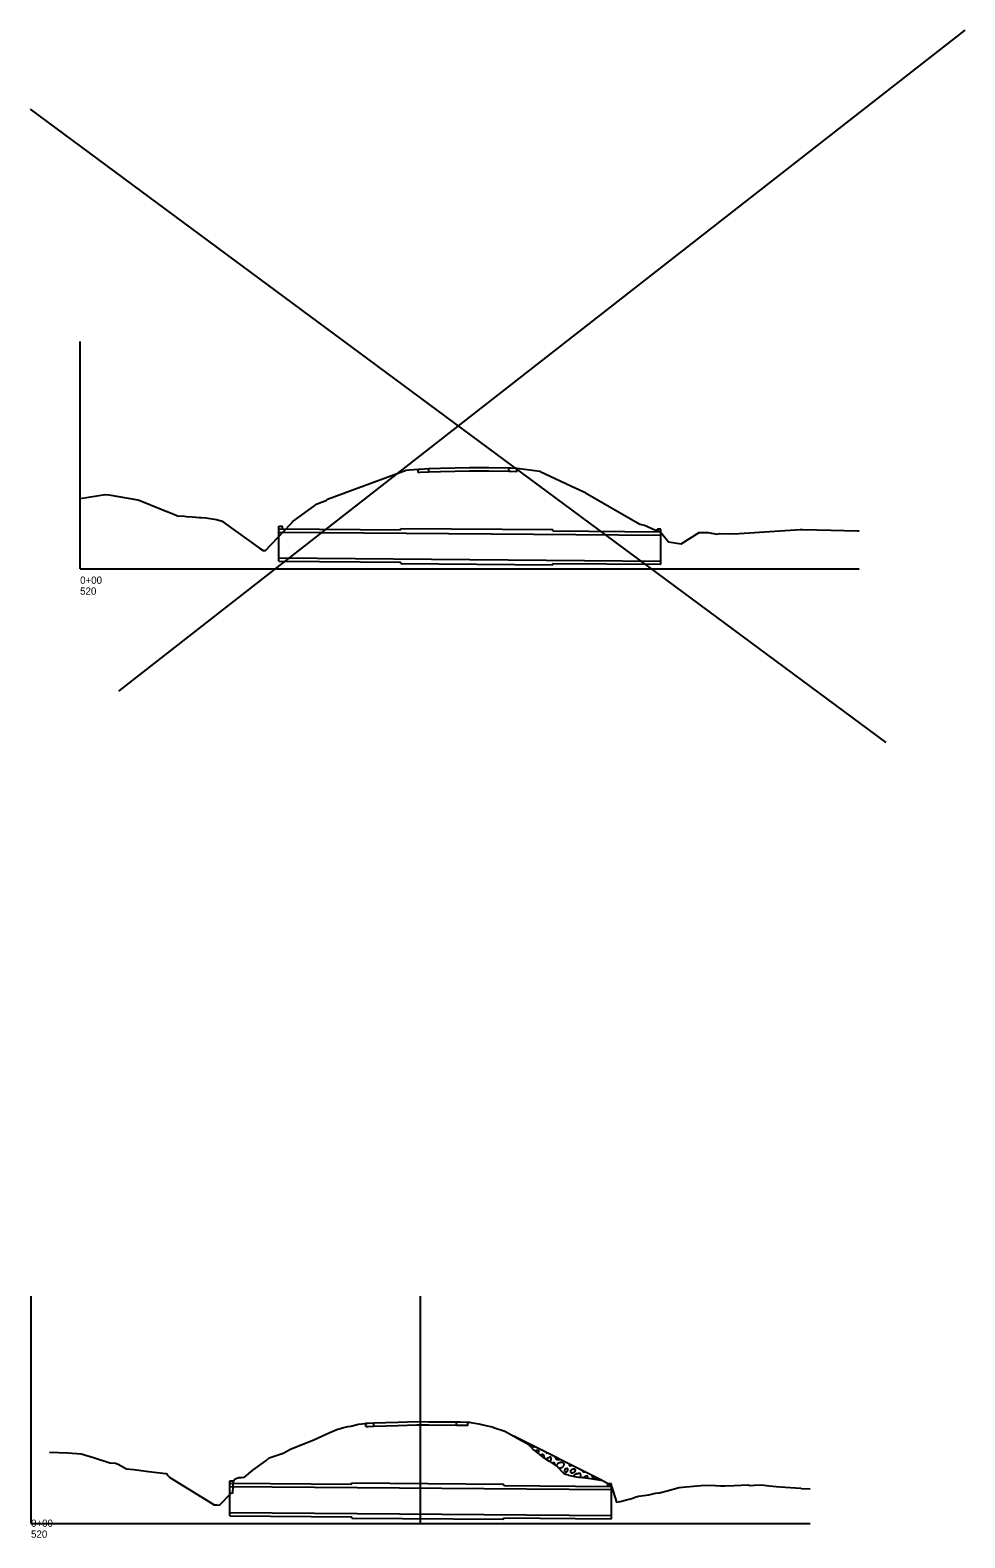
# Model space of a CAD drawing. Extents: x 2047712 to 2051245, y 280285 to 283042.
# Drawn here: x 2048516 to 2048876, y 282462 to 283042 of the extents above; entities that cross this region are included whole.
import ezdxf

# ---------------------------------------------------------------- set-up
doc = ezdxf.new("R2010")
doc.units = 0
for name, color, linetype in [('PM_X_Stop_Line', 7, 'Continuous'), ('PV_X_EOP', 7, 'Continuous'), ('SV_X_Mon_Cells_Found', 7, 'Continuous'), ('SV_X_Text', 7, 'Continuous'), ('UT_X_Water_Cells', 7, 'Continuous')]:
    doc.layers.add(name, color=color, linetype=linetype)

msp = doc.modelspace()

# ---------------------------------------------------------------- linework, layer by layer
at = {"layer": 'PM_X_Stop_Line'}
for p, q in [((2048875.63, 283042.02), (2048549.75, 282787.57)), ((2048515.73, 283011.56), (2048845.19, 282767.86)), ((2048534.97, 282834.64), (2048534.97, 282922.17)), ((2048534.97, 282834.64), (2048834.97, 282834.64)), ((2048516.07, 282467.2), (2048516.07, 282554.73)), ((2048666.07, 282467.2), (2048666.07, 282554.73)), ((2048516.07, 282467.2), (2048816.07, 282467.2))]:
    msp.add_line(p, q, dxfattribs=at)
at = {"layer": 'PV_X_EOP'}
for p, q in [((2048665.18, 282871.78), (2048665.18, 282873.03)), ((2048669.25, 282872.06), (2048669.25, 282873.31)), ((2048700.04, 282872.31), (2048700.04, 282873.56)), ((2048703.13, 282872.15), (2048703.13, 282873.4)), ((2048644.95, 282504.49), (2048644.95, 282505.74)), ((2048648.11, 282504.61), (2048648.11, 282505.86)), ((2048679.84, 282505.04), (2048679.84, 282506.29)), ((2048684.23, 282504.97), (2048684.23, 282506.22))]:
    msp.add_line(p, q, dxfattribs=at)
for points in [[(2048665.18, 282871.78), (2048665.89, 282871.84), (2048669.25, 282872.06), (2048673.74, 282872.15), (2048684.87, 282872.4), (2048692.39, 282872.41), (2048700.04, 282872.31), (2048700.87, 282872.3), (2048703.13, 282872.15), (2048703.13, 282872.15)], [(2048644.95, 282504.49), (2048645.82, 282504.52), (2048648.11, 282504.61), (2048657.25, 282504.88), (2048664.56, 282505.12), (2048669.3, 282505.09), (2048679.84, 282505.04), (2048681.33, 282505.02), (2048684.23, 282504.97), (2048684.23, 282504.97)]]:
    msp.add_lwpolyline(points, dxfattribs=at)
at = {"layer": 'SV_X_Mon_Cells_Found'}
for p, q in [((2048611.5, 282837.59), (2048611.5, 282851.09)), ((2048611.5, 282851.09), (2048612.94, 282851.09)), ((2048611.5, 282850.09), (2048658.5, 282849.71)), ((2048612.94, 282850.08), (2048612.94, 282851.09)), ((2048658.5, 282850.21), (2048717.03, 282849.74)), ((2048658.5, 282849.71), (2048658.5, 282850.21)), ((2048717.03, 282849.24), (2048717.03, 282849.74)), ((2048717.03, 282849.24), (2048758.53, 282848.91)), ((2048757.1, 282848.92), (2048757.1, 282849.91)), ((2048758.53, 282849.91), (2048757.1, 282849.91)), ((2048758.53, 282836.41), (2048758.53, 282849.91)), ((2048611.5, 282848.84), (2048758.53, 282847.66)), ((2048611.5, 282838.84), (2048758.53, 282837.66)), ((2048611.5, 282837.59), (2048658.5, 282837.21)), ((2048658.5, 282836.71), (2048658.5, 282837.21)), ((2048658.5, 282836.71), (2048717.03, 282836.24)), ((2048717.03, 282836.24), (2048717.03, 282836.74)), ((2048717.03, 282836.74), (2048758.53, 282836.41)), ((2048592.6, 282470.15), (2048592.6, 282483.65)), ((2048592.6, 282483.65), (2048594.03, 282483.65)), ((2048594.03, 282482.64), (2048594.03, 282483.65)), ((2048592.6, 282482.65), (2048639.6, 282482.27)), ((2048592.6, 282481.4), (2048739.62, 282480.22)), ((2048639.6, 282482.77), (2048698.12, 282482.3)), ((2048639.6, 282482.27), (2048639.6, 282482.77)), ((2048698.12, 282481.8), (2048698.12, 282482.3)), ((2048698.12, 282481.8), (2048739.62, 282481.47)), ((2048738.19, 282481.48), (2048738.19, 282482.47)), ((2048739.62, 282482.47), (2048738.19, 282482.47)), ((2048739.62, 282468.97), (2048739.62, 282482.47)), ((2048592.6, 282471.4), (2048739.62, 282470.22)), ((2048592.6, 282470.15), (2048639.6, 282469.77)), ((2048639.6, 282469.27), (2048639.6, 282469.77)), ((2048639.6, 282469.27), (2048698.12, 282468.8)), ((2048698.12, 282468.8), (2048698.12, 282469.3)), ((2048698.12, 282469.3), (2048739.62, 282468.97))]:
    msp.add_line(p, q, dxfattribs=at)
at = {"layer": 'SV_X_Text'}
msp.add_line((2048735.92, 282483.77), (2048701.95, 282500.76), dxfattribs=at)
for points, degree in [([(2048703.94, 282499.68), (2048703.93, 282499.71), (2048703.92, 282499.74), (2048703.92, 282499.78)], 2), ([(2048705.46, 282499.01), (2048705.42, 282499), (2048705.39, 282498.99), (2048705.35, 282498.98), (2048705.31, 282498.96), (2048705.26, 282498.95), (2048705.21, 282498.94)], 3), ([(2048710.03, 282496.72), (2048709.77, 282496.56), (2048709.42, 282496.5), (2048709.33, 282496.72), (2048709.28, 282496.85), (2048709.27, 282496.98), (2048709.26, 282497.11)], 3), ([(2048710.07, 282495.1), (2048710.18, 282495.16), (2048710.3, 282495.21), (2048710.41, 282495.27), (2048710.59, 282495.36), (2048710.81, 282495.38), (2048711.01, 282495.39), (2048711.16, 282495.39), (2048711.3, 282495.36), (2048711.43, 282495.22), (2048711.56, 282495.1), (2048711.54, 282494.94), (2048711.5, 282494.82), (2048711.45, 282494.61), (2048711.37, 282494.4), (2048711.17, 282494.23)], 3), ([(2048711.96, 282493.62), (2048712.01, 282493.63), (2048712.05, 282493.64), (2048712.1, 282493.65)], 2), ([(2048712.08, 282493.64), (2048712.39, 282493.69), (2048712.69, 282493.75), (2048712.99, 282493.79), (2048713.3, 282493.84), (2048713.44, 282493.32), (2048713.51, 282493.03), (2048713.56, 282492.87), (2048713.55, 282492.68), (2048713.49, 282492.5)], 3), ([(2048715, 282494.23), (2048714.78, 282494.19), (2048714.52, 282494.25), (2048714.43, 282494.43), (2048714.41, 282494.47), (2048714.4, 282494.5), (2048714.39, 282494.54)], 3), ([(2048714.5, 282491.86), (2048714.54, 282492), (2048714.62, 282492.16), (2048714.75, 282492.24), (2048714.87, 282492.32), (2048714.99, 282492.4), (2048715.12, 282492.48)], 3), ([(2048715.12, 282492.48), (2048715.35, 282492.58), (2048715.59, 282492.68), (2048715.82, 282492.78), (2048716.06, 282492.88), (2048716.18, 282492.35), (2048716.23, 282492.1), (2048716.29, 282491.84), (2048716.22, 282491.55), (2048716.01, 282491.29), (2048715.93, 282491.19), (2048715.84, 282491.12), (2048715.75, 282491.06)], 3), ([(2048716.73, 282490.42), (2048716.94, 282490.51), (2048717.14, 282490.59), (2048717.35, 282490.67), (2048717.51, 282490.73), (2048717.59, 282490.38), (2048717.6, 282490.24), (2048717.61, 282490.13), (2048717.57, 282490.02), (2048717.51, 282489.92)], 3), ([(2048719.82, 282491.83), (2048719.72, 282491.78), (2048719.61, 282491.75), (2048719.5, 282491.72), (2048719.22, 282491.63), (2048718.9, 282491.6), (2048718.62, 282491.72), (2048718.45, 282491.79), (2048718.32, 282491.92), (2048718.22, 282492.08), (2048718.1, 282492.26), (2048718.04, 282492.49), (2048718.06, 282492.7)], 3), ([(2048718.62, 282489.2), (2048718.6, 282489.25), (2048718.58, 282489.31), (2048718.57, 282489.36), (2048718.53, 282489.57), (2048718.64, 282489.81), (2048718.76, 282490), (2048718.85, 282490.14), (2048718.92, 282490.27), (2048719.04, 282490.38), (2048719.09, 282490.44), (2048719.14, 282490.49), (2048719.2, 282490.54)], 3), ([(2048719.2, 282490.54), (2048719.44, 282490.6), (2048719.67, 282490.66), (2048719.91, 282490.73), (2048720.26, 282490.82), (2048720.6, 282490.75), (2048720.95, 282490.46), (2048721.22, 282490.24), (2048721.24, 282489.91), (2048721.17, 282489.66), (2048721.08, 282489.34), (2048720.88, 282489.05), (2048720.57, 282488.79), (2048720.19, 282488.46), (2048719.67, 282488.34), (2048719.28, 282488.57), (2048719.25, 282488.58), (2048719.23, 282488.6), (2048719.2, 282488.61)], 3), ([(2048724.32, 282489.57), (2048724.07, 282489.34), (2048723.58, 282489.19), (2048723.47, 282489.46), (2048723.41, 282489.62), (2048723.4, 282489.78), (2048723.4, 282489.94), (2048723.4, 282489.97), (2048723.39, 282490.01), (2048723.39, 282490.04)], 3), ([(2048721.78, 282488.19), (2048722.03, 282488.23), (2048722.29, 282488.27), (2048722.54, 282488.3), (2048722.77, 282488.34), (2048722.82, 282487.84), (2048722.75, 282487.65), (2048722.67, 282487.43), (2048722.48, 282487.22), (2048722.27, 282487.06), (2048722.06, 282486.9), (2048721.62, 282486.93), (2048721.5, 282487.17), (2048721.42, 282487.33), (2048721.46, 282487.51), (2048721.5, 282487.66), (2048721.53, 282487.77), (2048721.55, 282487.9), (2048721.62, 282487.99), (2048721.67, 282488.06), (2048721.73, 282488.13), (2048721.78, 282488.19)], 3), ([(2048724.05, 282487.76), (2048724.22, 282487.84), (2048724.39, 282487.93), (2048724.55, 282488.01), (2048724.74, 282488.1), (2048724.96, 282488.12), (2048725.16, 282488.12), (2048725.3, 282488.13), (2048725.45, 282488.09), (2048725.58, 282487.96), (2048725.7, 282487.84), (2048725.68, 282487.68), (2048725.65, 282487.56), (2048725.59, 282487.35), (2048725.51, 282487.13), (2048725.3, 282486.96), (2048725.1, 282486.8), (2048724.89, 282486.77), (2048724.68, 282486.72), (2048724.45, 282486.67), (2048724.2, 282486.54), (2048723.97, 282486.73), (2048723.83, 282486.87), (2048723.8, 282487.02), (2048723.8, 282487.17), (2048723.81, 282487.3), (2048723.82, 282487.46), (2048723.91, 282487.57), (2048723.96, 282487.63), (2048724.01, 282487.7), (2048724.05, 282487.76)], 3), ([(2048725.13, 282485.34), (2048725.13, 282485.47), (2048725.15, 282485.6), (2048725.22, 282485.71), (2048725.32, 282485.87), (2048725.45, 282486.02), (2048725.63, 282486.13), (2048725.78, 282486.23), (2048725.92, 282486.31), (2048726.08, 282486.35), (2048726.13, 282486.36), (2048726.19, 282486.37), (2048726.24, 282486.38)], 3), ([(2048726.23, 282486.38), (2048726.53, 282486.43), (2048726.83, 282486.49), (2048727.14, 282486.53), (2048727.44, 282486.58), (2048727.58, 282486.06), (2048727.65, 282485.77), (2048727.72, 282485.52), (2048727.68, 282485.2), (2048727.46, 282484.96), (2048727.46, 282484.95), (2048727.45, 282484.95), (2048727.45, 282484.95)], 3), ([(2048729.35, 282487.06), (2048729.35, 282487.06), (2048729.34, 282487.06), (2048729.34, 282487.06), (2048729.13, 282486.9), (2048728.69, 282486.93), (2048728.57, 282487.17), (2048728.52, 282487.27), (2048728.52, 282487.37), (2048728.53, 282487.47)], 3), ([(2048728.73, 282484.8), (2048728.77, 282484.87), (2048728.82, 282484.93), (2048728.89, 282484.98), (2048729.01, 282485.06), (2048729.14, 282485.14), (2048729.26, 282485.22)], 3), ([(2048729.26, 282485.22), (2048729.49, 282485.32), (2048729.73, 282485.42), (2048729.96, 282485.52), (2048730.21, 282485.62), (2048730.32, 282485.09), (2048730.38, 282484.84), (2048730.39, 282484.76), (2048730.4, 282484.68), (2048730.39, 282484.6)], 3), ([(2048734.16, 282484.66), (2048733.99, 282484.57), (2048733.82, 282484.51), (2048733.64, 282484.45), (2048733.36, 282484.37), (2048733.04, 282484.34), (2048732.76, 282484.46), (2048732.59, 282484.53), (2048732.47, 282484.66), (2048732.36, 282484.82), (2048732.21, 282485.05), (2048732.15, 282485.37), (2048732.24, 282485.61)], 3), ([(2048735.89, 282483.78), (2048735.88, 282483.79), (2048735.87, 282483.79), (2048735.87, 282483.8)], 2)]:
    msp.add_open_spline(points, degree=degree, dxfattribs=at)
at = {"layer": 'UT_X_Water_Cells'}
for points in [[(2048534.97, 282861.77), (2048544.64, 282863.27), (2048546.05, 282863.17), (2048557.15, 282861.19), (2048557.99, 282860.95), (2048559.23, 282860.44), (2048565.49, 282857.92), (2048565.98, 282857.72), (2048566.4, 282857.55), (2048568.13, 282856.84), (2048571.06, 282855.69), (2048572.52, 282855.04), (2048575.17, 282854.9), (2048575.94, 282854.87), (2048578.13, 282854.63), (2048580.91, 282854.42), (2048581.52, 282854.38), (2048583.35, 282854.26), (2048587.49, 282853.7), (2048589.6, 282853.05), (2048590.77, 282852.1), (2048604.07, 282842.59), (2048605.48, 282841.75), (2048606.38, 282841.71), (2048615.96, 282851.91), (2048616.97, 282852.99), (2048626.28, 282859.65), (2048627.94, 282860.33), (2048629.7, 282861.01), (2048630.26, 282861.45), (2048639.58, 282864.88), (2048660.46, 282872.62), (2048660.65, 282872.66), (2048661.8, 282872.74), (2048665.18, 282873.03), (2048665.89, 282873.09), (2048669.25, 282873.31), (2048673.74, 282873.4), (2048684.87, 282873.65), (2048692.39, 282873.66), (2048700.04, 282873.56), (2048700.87, 282873.55), (2048703.13, 282873.4), (2048712, 282872.25), (2048712.02, 282872.24), (2048712.03, 282872.24), (2048712.06, 282872.23), (2048712.14, 282872.19), (2048725.82, 282865.7), (2048726.77, 282865.35), (2048728.96, 282864.3), (2048729.14, 282864.21), (2048729.59, 282863.92), (2048750.52, 282851.88), (2048752.32, 282851.51), (2048756.21, 282849.72), (2048757.71, 282849.29), (2048758.26, 282848.97), (2048761.58, 282845.07), (2048766.34, 282844.29), (2048773.31, 282848.63), (2048776.73, 282848.59), (2048780.19, 282848.02), (2048781.23, 282848.26), (2048786.77, 282848.13), (2048812.28, 282849.84), (2048813.06, 282849.82), (2048824.09, 282849.55), (2048834.35, 282849.29), (2048834.97, 282849.24)], [(2048523.14, 282494.57), (2048530.29, 282494.4), (2048535.33, 282493.99), (2048540.08, 282492.56), (2048546.43, 282490.54), (2048548.56, 282490.43), (2048549.62, 282489.97), (2048552.8, 282488.25), (2048555.67, 282487.9), (2048557.55, 282487.64), (2048561.29, 282487.18), (2048567.91, 282486.38), (2048568.34, 282486.33), (2048568.47, 282485.95), (2048569.53, 282484.89), (2048583.51, 282476.28), (2048586.58, 282474.31), (2048587.62, 282474.4), (2048588.64, 282474.18), (2048593.15, 282478.8), (2048593.73, 282479.03), (2048594, 282483.61), (2048594.72, 282484.31), (2048596.11, 282484.84), (2048597.16, 282484.91), (2048598.26, 282484.95), (2048601.42, 282487.68), (2048606.46, 282491.23), (2048607.82, 282492.39), (2048609.68, 282493.09), (2048613.14, 282494.29), (2048616.03, 282495.74), (2048625.17, 282499.52), (2048631.17, 282502.18), (2048633.86, 282503.34), (2048635.94, 282503.93), (2048637.99, 282504.46), (2048639.2, 282504.57), (2048642.1, 282505.39), (2048644.6, 282505.64), (2048644.95, 282505.74), (2048645.82, 282505.77), (2048648.11, 282505.86), (2048657.25, 282506.13), (2048664.56, 282506.37), (2048669.3, 282506.34), (2048679.84, 282506.29), (2048681.33, 282506.27), (2048684.23, 282506.22), (2048684.32, 282506.2), (2048684.93, 282506.15), (2048685.42, 282506.01), (2048688.5, 282505.57), (2048691.2, 282504.92), (2048693.59, 282504.32), (2048694.55, 282504.02), (2048697.7, 282502.95), (2048698.46, 282502.66), (2048700.76, 282501.4), (2048703.76, 282499.78), (2048706.27, 282498.32), (2048707.68, 282497.52), (2048707.99, 282497.22), (2048709.63, 282495.42), (2048710.07, 282495.1), (2048712.97, 282492.82), (2048715.53, 282491.2), (2048718.71, 282489.14), (2048720.98, 282486.71), (2048721.39, 282486.31), (2048722.83, 282485.84), (2048723, 282485.77), (2048724.14, 282485.54), (2048725.95, 282485.18), (2048726.91, 282485.01), (2048727.49, 282484.94), (2048731.47, 282484.47), (2048735.44, 282483.85), (2048735.92, 282483.77), (2048736.17, 282483.68), (2048738.23, 282482.59), (2048739.01, 282481.79), (2048739.19, 282482.09), (2048739.65, 282481.15), (2048741.49, 282475.35), (2048742.97, 282475.67), (2048745.33, 282476.23), (2048746.88, 282476.71), (2048747.84, 282476.96), (2048748.89, 282477.39), (2048749.07, 282477.48), (2048749.57, 282477.57), (2048749.97, 282477.65), (2048753.94, 282478.26), (2048756.57, 282478.84), (2048758.07, 282479.01), (2048761.01, 282479.7), (2048765.69, 282481.06), (2048768.13, 282481.23), (2048775.63, 282481.93), (2048779.59, 282481.8), (2048781.49, 282481.66), (2048783.23, 282481.72), (2048786.85, 282481.76), (2048792.11, 282482.03), (2048793.02, 282481.75), (2048794.66, 282481.97), (2048797.39, 282482), (2048800.31, 282481.61), (2048803.01, 282481.38), (2048806.41, 282481.21), (2048812.47, 282480.71), (2048812.61, 282480.7), (2048812.71, 282480.69), (2048812.75, 282480.69), (2048816.07, 282480.51)]]:
    msp.add_lwpolyline(points, dxfattribs=at)

# ---------------------------------------------------------------- texts
at = {"layer": 'PM_X_Stop_Line'}
for s, p in [('0+00', (2048534.97, 282828.9)), ('520', (2048534.97, 282824.7)), ('0+00', (2048516.07, 282465.88)), ('520', (2048516.07, 282461.68))]:
    msp.add_text(s, height=2.8, dxfattribs=at).set_placement(p)

doc.saveas('drawing.dxf')
